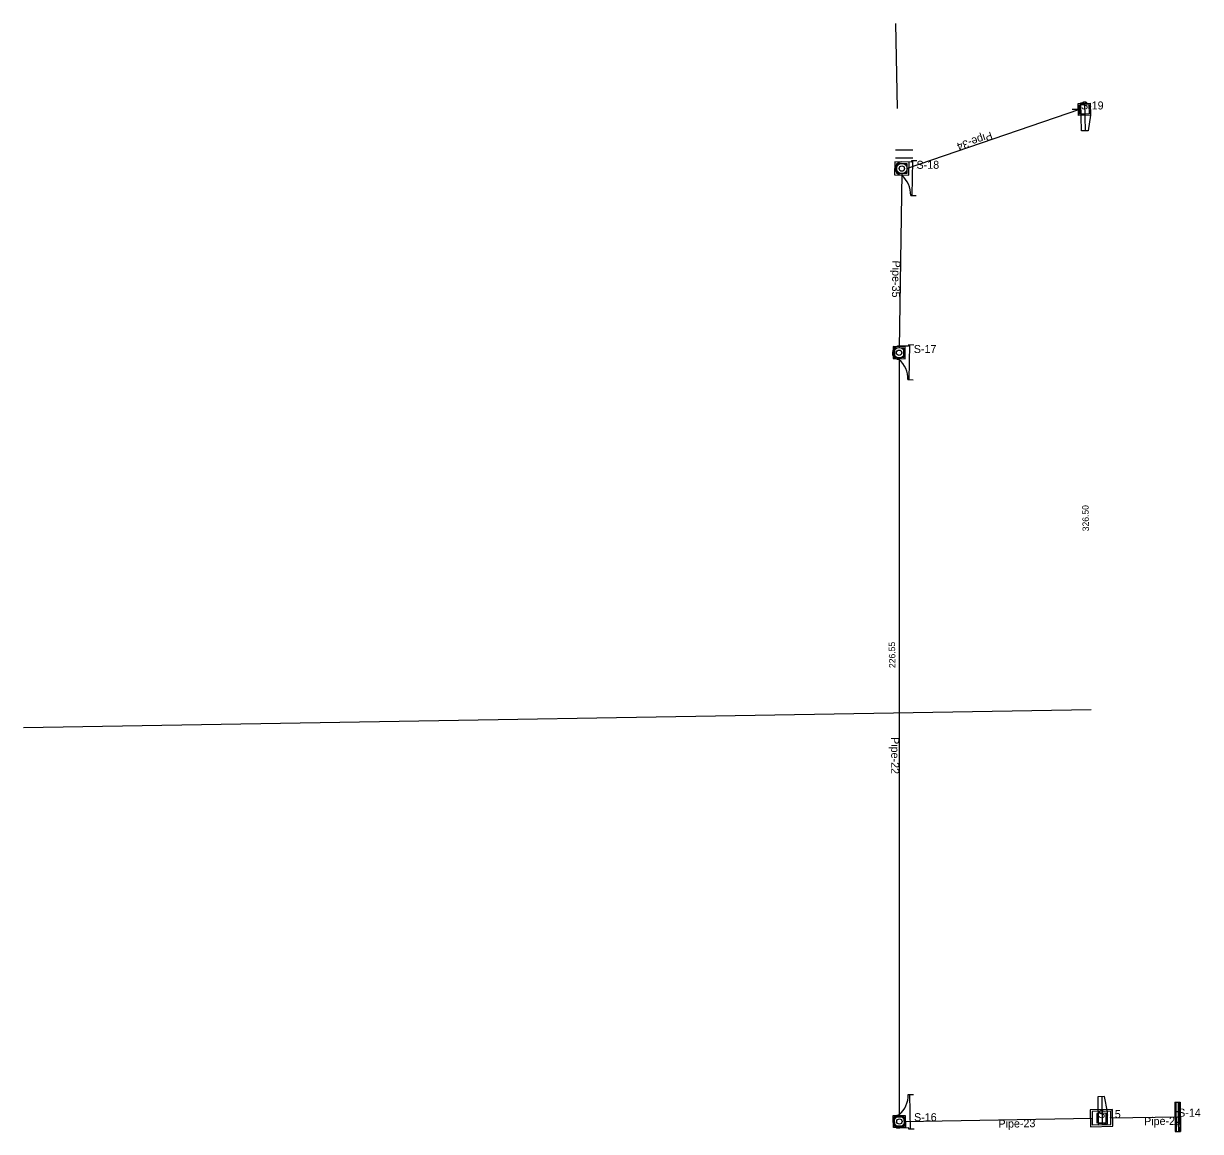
# Model space of a CAD drawing. Extents: x 925371 to 925937, y 853654 to 858024.
# Drawn here: x 925439.2 to 925880.2, y 854396.1 to 854811.3 of the extents above; entities that cross this region are included whole.
import ezdxf

# ---------------------------------------------------------------- set-up
doc = ezdxf.new("R2010")
doc.units = 0
for name, color, linetype in [('Endwall', 7, 'Continuous'), ('GPKDrBack_dp', 7, 'Continuous'), ('GPKDrBottom_dp', 7, 'Continuous'), ('GPKDrCellIns_dp', 7, 'Continuous'), ('GPKDrCentroid_dp', 7, 'Continuous'), ('GPKDrFront_dp', 7, 'Continuous'), ('GPKDrPipe_dp', 7, 'Continuous'), ('GPKDrPipeCir_dp', 7, 'Continuous'), ('InletBottomJ', 7, 'Continuous'), ('InletBottomP', 7, 'Continuous'), ('InletCurb', 7, 'Continuous'), ('Miscellaneous5', 7, 'Continuous'), ('NonPlottingEle_dp', 7, 'Continuous'), ('PipeCulvert', 7, 'Continuous'), ('Scratch1_dp', 7, 'Continuous')]:
    doc.layers.add(name, color=color, linetype=linetype)

msp = doc.modelspace()

# ---------------------------------------------------------------- linework, layer by layer
at = {"layer": 'Endwall'}
for p, q in [((925870.62, 854407.13), (925872.62, 854407.16)), ((925870.62, 854407.13), (925870.81, 854396.13)), ((925870.95, 854407.14), (925871.14, 854396.14)), ((925871.88, 854407.15), (925871.85, 854403.65)), ((925872.29, 854407.16), (925872.47, 854396.16)), ((925872.62, 854407.16), (925872.81, 854396.17)), ((925871.01, 854403.64), (925871.85, 854403.65)), ((925871.85, 854403.65), (925871.92, 854399.65)), ((925870.81, 854396.13), (925872.81, 854396.17)), ((925871.08, 854399.64), (925871.92, 854399.65)), ((925871.92, 854399.65), (925872.06, 854396.15))]:
    msp.add_line(p, q, dxfattribs=at)
at = {"layer": 'GPKDrBack_dp'}
for p, q in [((925838.46, 854779.14), (925838.46, 854779.14)), ((925838.96, 854779.15), (925838.96, 854779.15)), ((925765.83, 854756.99), (925765.83, 854756.99)), ((925766.33, 854756.98), (925766.33, 854756.98)), ((925764.8, 854687.96), (925764.8, 854687.96)), ((925765.55, 854687.95), (925765.55, 854687.95)), ((925845.39, 854401.2), (925845.39, 854401.2)), ((925846.63, 854401.22), (925846.63, 854401.22)), ((925871.05, 854401.64), (925871.05, 854401.64)), ((925764.9, 854399.83), (925764.9, 854399.83)), ((925765.65, 854399.84), (925765.65, 854399.84))]:
    msp.add_line(p, q, dxfattribs=at)
at = {"layer": 'GPKDrBottom_dp'}
for p, q in [((925834.93, 854780.83), (925834.93, 854780.83)), ((925834.93, 854780.83), (925834.93, 854780.83)), ((925836.68, 854780.86), (925836.68, 854780.86)), ((925836.68, 854780.86), (925836.68, 854780.86)), ((925838.43, 854780.89), (925838.43, 854780.89)), ((925838.43, 854780.89), (925838.43, 854780.89)), ((925834.96, 854779.08), (925834.96, 854779.08)), ((925834.96, 854779.08), (925834.96, 854779.08)), ((925834.99, 854777.33), (925834.99, 854777.33)), ((925834.99, 854777.33), (925834.99, 854777.33)), ((925836.71, 854779.11), (925836.71, 854779.11)), ((925836.71, 854779.11), (925836.71, 854779.11)), ((925836.74, 854777.36), (925836.74, 854777.36)), ((925836.74, 854777.36), (925836.74, 854777.36)), ((925838.46, 854779.14), (925838.46, 854779.14)), ((925838.46, 854779.14), (925838.46, 854779.14)), ((925838.49, 854777.39), (925838.49, 854777.39)), ((925838.49, 854777.39), (925838.49, 854777.39)), ((925766.36, 854758.73), (925766.36, 854758.73)), ((925766.94, 854758.38), (925766.94, 854758.38)), ((925768.36, 854758.94), (925768.36, 854758.94)), ((925768.36, 854758.69), (925768.36, 854758.69)), ((925769.77, 854758.33), (925769.77, 854758.33)), ((925770.36, 854758.66), (925770.36, 854758.66)), ((925766.3, 854755.23), (925766.3, 854755.23)), ((925766.33, 854756.98), (925766.33, 854756.98)), ((925766.33, 854756.98), (925766.33, 854756.98)), ((925766.89, 854755.55), (925766.89, 854755.55)), ((925768.29, 854755.19), (925768.29, 854755.19)), ((925768.29, 854754.94), (925768.29, 854754.94)), ((925768.33, 854756.94), (925768.33, 854756.94)), ((925768.33, 854756.94), (925768.33, 854756.94)), ((925769.71, 854755.5), (925769.71, 854755.5)), ((925770.29, 854755.16), (925770.29, 854755.16)), ((925770.33, 854756.91), (925770.33, 854756.91)), ((925770.33, 854756.91), (925770.33, 854756.91)), ((925765.3, 854687.95), (925765.3, 854687.95)), ((925765.55, 854687.95), (925765.55, 854687.95)), ((925765.58, 854689.7), (925765.58, 854689.7)), ((925765.91, 854689.35), (925765.91, 854689.35)), ((925767.3, 854687.91), (925767.3, 854687.91)), ((925767.3, 854687.91), (925767.3, 854687.91)), ((925767.33, 854689.66), (925767.33, 854689.66)), ((925767.34, 854689.91), (925767.34, 854689.91)), ((925768.74, 854689.3), (925768.74, 854689.3)), ((925769.05, 854687.88), (925769.05, 854687.88)), ((925769.08, 854689.63), (925769.08, 854689.63)), ((925769.3, 854687.88), (925769.3, 854687.88)), ((925765.52, 854686.2), (925765.52, 854686.2)), ((925765.86, 854686.53), (925765.86, 854686.53)), ((925767.26, 854685.91), (925767.26, 854685.91)), ((925767.27, 854686.16), (925767.27, 854686.16)), ((925768.69, 854686.47), (925768.69, 854686.47)), ((925769.02, 854686.13), (925769.02, 854686.13)), ((925765.62, 854401.59), (925765.62, 854401.59)), ((925765.96, 854401.26), (925765.96, 854401.26)), ((925767.36, 854401.87), (925767.36, 854401.87)), ((925767.37, 854401.62), (925767.37, 854401.62)), ((925768.79, 854401.31), (925768.79, 854401.31)), ((925769.12, 854401.65), (925769.12, 854401.65)), ((925839.59, 854403.6), (925839.59, 854403.6)), ((925839.64, 854401.1), (925839.64, 854401.1)), ((925841.36, 854402.88), (925841.36, 854402.88)), ((925841.39, 854401.13), (925841.39, 854401.13)), ((925843.09, 854403.66), (925843.09, 854403.66)), ((925843.11, 854402.91), (925843.11, 854402.91)), ((925843.14, 854401.16), (925843.14, 854401.16)), ((925843.14, 854401.16), (925843.14, 854401.16)), ((925844.86, 854402.94), (925844.86, 854402.94)), ((925844.89, 854401.19), (925844.89, 854401.19)), ((925846.59, 854403.72), (925846.59, 854403.72)), ((925846.63, 854401.22), (925846.63, 854401.22)), ((925871.88, 854401.65), (925871.88, 854401.65)), ((925765.4, 854399.84), (925765.4, 854399.84)), ((925765.65, 854399.84), (925765.65, 854399.84)), ((925765.68, 854398.09), (925765.68, 854398.09)), ((925766.01, 854398.44), (925766.01, 854398.44)), ((925767.4, 854399.87), (925767.4, 854399.87)), ((925767.4, 854399.87), (925767.4, 854399.87)), ((925767.43, 854398.12), (925767.43, 854398.12)), ((925767.43, 854397.87), (925767.43, 854397.87)), ((925768.83, 854398.48), (925768.83, 854398.48)), ((925769.15, 854399.9), (925769.15, 854399.9)), ((925769.18, 854398.15), (925769.18, 854398.15)), ((925769.4, 854399.91), (925769.4, 854399.91)), ((925839.68, 854398.6), (925839.68, 854398.6)), ((925841.42, 854399.38), (925841.42, 854399.38)), ((925843.17, 854399.41), (925843.17, 854399.41)), ((925843.18, 854398.66), (925843.18, 854398.66)), ((925844.91, 854399.44), (925844.91, 854399.44)), ((925846.68, 854398.72), (925846.68, 854398.72))]:
    msp.add_line(p, q, dxfattribs=at)
at = {"layer": 'GPKDrCellIns_dp'}
for p, q in [((925835.46, 854779.09), (925835.46, 854779.09)), ((925836.71, 854779.11), (925836.71, 854779.11)), ((925768.33, 854756.94), (925768.33, 854756.94)), ((925773.83, 854756.84), (925773.83, 854756.84)), ((925767.3, 854687.91), (925767.3, 854687.91)), ((925772.8, 854687.82), (925772.8, 854687.82)), ((925841.89, 854401.14), (925841.89, 854401.14)), ((925843.14, 854401.16), (925843.14, 854401.16)), ((925871.88, 854401.65), (925871.88, 854401.65)), ((925767.4, 854399.87), (925767.4, 854399.87)), ((925772.9, 854399.97), (925772.9, 854399.97))]:
    msp.add_line(p, q, dxfattribs=at)
at = {"layer": 'GPKDrCentroid_dp'}
for p, q in [((925836.71, 854779.11), (925836.71, 854779.11)), ((925768.33, 854756.94), (925768.33, 854756.94)), ((925768.33, 854756.94), (925768.33, 854756.94)), ((925767.3, 854687.91), (925767.3, 854687.91)), ((925843.14, 854401.16), (925843.14, 854401.16)), ((925843.14, 854401.16), (925843.14, 854401.16)), ((925767.4, 854399.87), (925767.4, 854399.87))]:
    msp.add_line(p, q, dxfattribs=at)
at = {"layer": 'GPKDrFront_dp'}
for p, q in [((925834.96, 854779.08), (925834.96, 854779.08)), ((925835.46, 854779.09), (925835.46, 854779.09)), ((925770.33, 854756.91), (925770.33, 854756.91)), ((925773.83, 854756.84), (925773.83, 854756.84)), ((925769.05, 854687.88), (925769.05, 854687.88)), ((925772.8, 854687.82), (925772.8, 854687.82)), ((925839.64, 854401.1), (925839.64, 854401.1)), ((925841.89, 854401.14), (925841.89, 854401.14)), ((925871.88, 854401.65), (925871.88, 854401.65)), ((925769.15, 854399.9), (925769.15, 854399.9)), ((925772.9, 854399.97), (925772.9, 854399.97))]:
    msp.add_line(p, q, dxfattribs=at)
at = {"layer": 'GPKDrPipe_dp'}
for p, q in [((925836.68, 854780.86), (925836.68, 854780.86)), ((925836.68, 854780.86), (925836.68, 854780.86)), ((925834.96, 854779.08), (925834.96, 854779.08)), ((925834.96, 854779.08), (925834.96, 854779.08)), ((925836.74, 854777.36), (925836.74, 854777.36)), ((925836.74, 854777.36), (925836.74, 854777.36)), ((925838.46, 854779.14), (925838.46, 854779.14)), ((925838.46, 854779.14), (925838.46, 854779.14)), ((925766.51, 854757.78), (925766.51, 854757.78)), ((925766.96, 854758.4), (925766.96, 854758.4)), ((925767.61, 854758.81), (925767.61, 854758.81)), ((925768.36, 854758.94), (925768.36, 854758.94)), ((925768.36, 854758.69), (925768.36, 854758.69)), ((925769.16, 854758.76), (925769.16, 854758.76)), ((925769.79, 854758.31), (925769.79, 854758.31)), ((925766.33, 854756.98), (925766.33, 854756.98)), ((925766.33, 854756.98), (925766.33, 854756.98)), ((925766.46, 854756.22), (925766.46, 854756.22)), ((925766.87, 854755.57), (925766.87, 854755.57)), ((925767.49, 854755.13), (925767.49, 854755.13)), ((925768.29, 854755.19), (925768.29, 854755.19)), ((925768.29, 854754.94), (925768.29, 854754.94)), ((925769.04, 854755.08), (925769.04, 854755.08)), ((925769.69, 854755.48), (925769.69, 854755.48)), ((925770.14, 854756.1), (925770.14, 854756.1)), ((925770.19, 854757.66), (925770.19, 854757.66)), ((925770.33, 854756.91), (925770.33, 854756.91)), ((925770.33, 854756.91), (925770.33, 854756.91)), ((925765.3, 854687.95), (925765.3, 854687.95)), ((925765.43, 854687.2), (925765.43, 854687.2)), ((925765.48, 854688.75), (925765.48, 854688.75)), ((925765.55, 854687.95), (925765.55, 854687.95)), ((925765.93, 854689.37), (925765.93, 854689.37)), ((925766.58, 854689.78), (925766.58, 854689.78)), ((925767.33, 854689.66), (925767.33, 854689.66)), ((925767.34, 854689.91), (925767.34, 854689.91)), ((925768.14, 854689.73), (925768.14, 854689.73)), ((925768.76, 854689.28), (925768.76, 854689.28)), ((925769.05, 854687.88), (925769.05, 854687.88)), ((925769.17, 854688.63), (925769.17, 854688.63)), ((925769.3, 854687.88), (925769.3, 854687.88)), ((925765.84, 854686.55), (925765.84, 854686.55)), ((925766.46, 854686.1), (925766.46, 854686.1)), ((925767.26, 854685.91), (925767.26, 854685.91)), ((925767.27, 854686.16), (925767.27, 854686.16)), ((925768.02, 854686.05), (925768.02, 854686.05)), ((925768.67, 854686.45), (925768.67, 854686.45)), ((925769.12, 854687.08), (925769.12, 854687.08)), ((925765.53, 854400.59), (925765.53, 854400.59)), ((925765.94, 854401.24), (925765.94, 854401.24)), ((925766.56, 854401.69), (925766.56, 854401.69)), ((925767.36, 854401.87), (925767.36, 854401.87)), ((925767.37, 854401.62), (925767.37, 854401.62)), ((925768.12, 854401.74), (925768.12, 854401.74)), ((925768.77, 854401.33), (925768.77, 854401.33)), ((925769.21, 854400.71), (925769.21, 854400.71)), ((925839.64, 854401.1), (925839.64, 854401.1)), ((925841.39, 854401.13), (925841.39, 854401.13)), ((925843.09, 854403.66), (925843.09, 854403.66)), ((925843.11, 854402.91), (925843.11, 854402.91)), ((925844.89, 854401.19), (925844.89, 854401.19)), ((925846.63, 854401.22), (925846.63, 854401.22)), ((925871.55, 854401.65), (925871.55, 854401.65)), ((925765.4, 854399.84), (925765.4, 854399.84)), ((925765.58, 854399.04), (925765.58, 854399.04)), ((925765.65, 854399.84), (925765.65, 854399.84)), ((925766.03, 854398.42), (925766.03, 854398.42)), ((925766.68, 854398.01), (925766.68, 854398.01)), ((925767.43, 854398.12), (925767.43, 854398.12)), ((925767.43, 854397.87), (925767.43, 854397.87)), ((925768.23, 854398.06), (925768.23, 854398.06)), ((925768.85, 854398.51), (925768.85, 854398.51)), ((925769.15, 854399.9), (925769.15, 854399.9)), ((925769.26, 854399.15), (925769.26, 854399.15)), ((925769.4, 854399.91), (925769.4, 854399.91)), ((925843.17, 854399.41), (925843.17, 854399.41)), ((925843.18, 854398.66), (925843.18, 854398.66))]:
    msp.add_line(p, q, dxfattribs=at)
at = {"layer": 'GPKDrPipeCir_dp'}
for points in [[(925834.99, 854777.33), (925834.93, 854780.83), (925838.43, 854780.89), (925838.49, 854777.39)], [(925841.36, 854402.88), (925841.42, 854399.38), (925844.91, 854399.44), (925844.86, 854402.94)]]:
    msp.add_lwpolyline(points, close=True, dxfattribs=at)
for centre in [(925768.33, 854756.94), (925767.3, 854687.91), (925767.4, 854399.87)]:
    msp.add_circle(centre, 2, dxfattribs=at)
at = {"layer": 'InletBottomJ'}
for p, q in [((925765.7, 854759.41), (925765.62, 854754.57)), ((925771.04, 854759.31), (925765.7, 854759.41)), ((925766.36, 854758.73), (925766.3, 854755.23)), ((925770.36, 854758.66), (925766.36, 854758.73)), ((925770.29, 854755.16), (925770.36, 854758.66)), ((925770.95, 854754.48), (925771.04, 854759.31)), ((925765.62, 854754.57), (925770.95, 854754.48)), ((925766.3, 854755.23), (925770.29, 854755.16))]:
    msp.add_line(p, q, dxfattribs=at)
for points in [[(925847.36, 854398.07), (925847.25, 854404.4), (925838.92, 854404.26), (925839.02, 854397.92)], [(925846.59, 854403.72), (925839.59, 854403.6), (925839.68, 854398.6), (925846.68, 854398.72)]]:
    msp.add_lwpolyline(points, close=True, dxfattribs=at)
at = {"layer": 'InletBottomP'}
for points in [[(925838.92, 854781.4), (925839, 854776.9), (925834.5, 854776.82), (925834.42, 854781.32)], [(925834.93, 854780.83), (925838.43, 854780.89), (925838.49, 854777.39), (925834.99, 854777.33)], [(925765.09, 854690.2), (925765.01, 854685.7), (925769.51, 854685.62), (925769.59, 854690.12)], [(925769.08, 854689.63), (925765.58, 854689.7), (925765.52, 854686.2), (925769.02, 854686.13)], [(925765.18, 854397.59), (925765.11, 854402.09), (925769.61, 854402.16), (925769.68, 854397.66)], [(925769.18, 854398.15), (925765.68, 854398.09), (925765.62, 854401.59), (925769.12, 854401.65)]]:
    msp.add_lwpolyline(points, close=True, dxfattribs=at)
at = {"layer": 'InletCurb'}
for p, q in [((925835.42, 854781.59), (925837.42, 854781.62)), ((925835.6, 854771.09), (925835.42, 854781.59)), ((925835.43, 854781.03), (925836.93, 854781.06)), ((925837.1, 854771.11), (925836.92, 854781.61)), ((925837.42, 854781.62), (925837.42, 854781.37)), ((925837.42, 854781.37), (925838.92, 854781.4)), ((925838.92, 854781.4), (925839, 854776.9)), ((925835.49, 854777.13), (925836.99, 854777.15)), ((925839, 854776.9), (925838.09, 854771.13)), ((925838.09, 854771.13), (925835.6, 854771.09)), ((925771.87, 854759.38), (925768.37, 854759.44)), ((925771.88, 854759.88), (925771.87, 854759.38)), ((925773.88, 854759.84), (925771.88, 854759.88)), ((925772.15, 854746.87), (925772.38, 854759.87)), ((925771.65, 854746.88), (925773.65, 854746.84)), ((925770.84, 854690.35), (925767.34, 854690.41)), ((925770.85, 854690.85), (925770.84, 854690.35)), ((925772.85, 854690.82), (925770.85, 854690.85)), ((925771.12, 854677.84), (925771.35, 854690.84)), ((925770.62, 854677.85), (925772.62, 854677.82)), ((925770.73, 854409.93), (925772.73, 854409.97)), ((925771.23, 854409.94), (925771.45, 854396.94)), ((925844.25, 854409.18), (925841.75, 854409.14)), ((925841.75, 854409.14), (925841.93, 854398.64)), ((925843.25, 854409.17), (925843.43, 854398.67)), ((925845.35, 854403.45), (925844.25, 854409.18)), ((925841.85, 854403.1), (925843.35, 854403.12)), ((925845.42, 854398.95), (925845.35, 854403.45)), ((925770.94, 854397.43), (925767.44, 854397.37)), ((925770.95, 854396.93), (925770.94, 854397.43)), ((925772.95, 854396.97), (925770.95, 854396.93)), ((925841.92, 854399.19), (925843.42, 854399.22)), ((925841.93, 854398.64), (925843.93, 854398.68)), ((925843.92, 854398.93), (925845.42, 854398.95)), ((925843.93, 854398.68), (925843.92, 854398.93))]:
    msp.add_line(p, q, dxfattribs=at)
for centre in [(925768.33, 854756.94), (925767.3, 854687.91), (925767.4, 854399.87)]:
    msp.add_circle(centre, 1, dxfattribs=at)
for centre, radius, start, end in [((925768.33, 854756.94), 2.5, 88.9741, 268.9741), ((925761.65, 854746.96), 10, 359.5458, 48.4363), ((925767.3, 854687.91), 2.5, 88.9741, 268.9741), ((925760.62, 854677.93), 10, 359.5458, 48.4363), ((925760.73, 854409.86), 10, 311.512, 0.4024), ((925767.4, 854399.87), 2.5, 90.9741, 270.9741)]:
    msp.add_arc(centre, radius, start, end, dxfattribs=at)
at = {"layer": 'Miscellaneous5'}
msp.add_line((925839.28, 854554.12), (925439.15, 854547.32), dxfattribs=at)
at = {"layer": 'PipeCulvert'}
for p, q in [((925834.96, 854779.08), (925770.33, 854756.91)), ((925768.29, 854755.19), (925767.33, 854689.66)), ((925767.27, 854686.16), (925767.37, 854401.62)), ((925769.4, 854399.91), (925839.64, 854401.1)), ((925846.63, 854401.22), (925871.55, 854401.65))]:
    msp.add_line(p, q, dxfattribs=at)
at = {"layer": 'Scratch1_dp'}
for p, q in [((925766.67, 854779.38), (925766.13, 854811.27)), ((925834.96, 854779.08), (925832.16, 854779.03)), ((925772.43, 854763.77), (925765.93, 854763.87)), ((925772.39, 854760.77), (925765.89, 854760.87))]:
    msp.add_line(p, q, dxfattribs=at)

# ---------------------------------------------------------------- texts
at = {"layer": 'NonPlottingEle_dp'}
for s, p in [('S-19', (925835.46, 854779.09)), ('S-18', (925773.83, 854756.84)), ('S-17', (925772.8, 854687.82)), ('S-16', (925772.9, 854399.97)), ('S-15', (925841.89, 854401.14)), ('S-14', (925871.88, 854401.65))]:
    msp.add_text(s, height=3, dxfattribs=at).set_placement(p)
for s, height, rotation, p in [('Pipe-34', 3, 198.9339, (925801.67, 854770.83)), ('Pipe-35', 3, 269.1572, (925764.81, 854722.47)), ('326.50', 2.4, 90.9741, (925838.46, 854621.04)), ('226.55', 2.4, 90.9741, (925765.94, 854569.8)), ('Pipe-22', 3, 270.0198, (925764.32, 854543.89)), ('Pipe-23', 3, 0.9741, (925804.57, 854397.51)), ('Pipe-20', 3, 0.9741, (925859.14, 854398.43))]:
    msp.add_text(s, height=height, rotation=rotation, dxfattribs=at).set_placement(p)

doc.saveas('drawing.dxf')
